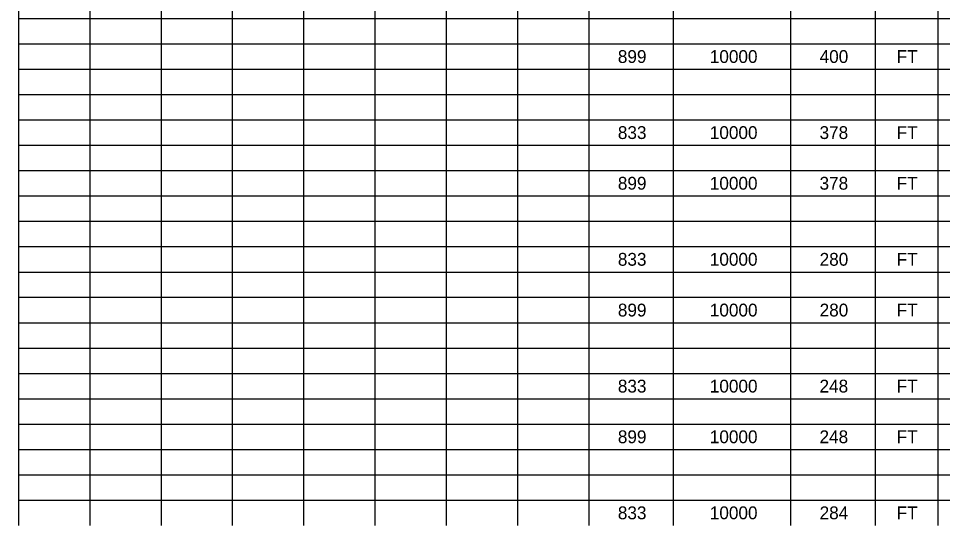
# Model space of a CAD drawing. Extents: x 0.2 to 34.2, y 0 to 22.
# Drawn here: x 13.45 to 23.52, y 10.48 to 16.02 of the extents above; entities that cross this region are included whole.
import ezdxf

# ---------------------------------------------------------------- set-up
doc = ezdxf.new("R2010")
doc.units = 0
doc.layers.add('Default', color=7, linetype='Continuous')

msp = doc.modelspace()

# ---------------------------------------------------------------- linework, layer by layer
at = {"layer": 'Default'}
for p, q in [((13.445, 16.294), (13.445, 16.018)), ((14.223, 16.294), (14.223, 16.018)), ((15, 16.294), (15, 16.018)), ((15.778, 16.294), (15.778, 16.018)), ((16.555, 16.294), (16.555, 16.018)), ((17.332, 16.294), (17.332, 16.018)), ((18.11, 16.294), (18.11, 16.018)), ((18.887, 16.294), (18.887, 16.018)), ((19.665, 16.294), (19.665, 16.018)), ((20.587, 16.294), (20.587, 16.018)), ((21.865, 16.294), (21.865, 16.018)), ((22.788, 16.294), (22.788, 16.018)), ((23.473, 16.294), (23.473, 16.018)), ((13.445, 16.018), (14.223, 16.018)), ((13.445, 16.018), (13.445, 15.741)), ((14.223, 16.018), (16.555, 16.018)), ((14.223, 16.018), (14.223, 15.741)), ((15, 16.018), (15, 15.741)), ((15.778, 16.018), (15.778, 15.741)), ((16.555, 16.018), (32.196, 16.018)), ((16.555, 16.018), (16.555, 15.741)), ((17.332, 16.018), (17.332, 15.741)), ((18.11, 16.018), (18.11, 15.741)), ((18.887, 16.018), (18.887, 15.741)), ((19.665, 16.018), (19.665, 15.741)), ((20.587, 16.018), (20.587, 15.741)), ((21.865, 16.018), (21.865, 15.741)), ((22.788, 16.018), (22.788, 15.741)), ((23.473, 16.018), (23.473, 15.741)), ((13.445, 15.741), (14.223, 15.741)), ((13.445, 15.741), (13.445, 15.464)), ((14.223, 15.741), (16.555, 15.741)), ((14.223, 15.741), (14.223, 15.464)), ((15, 15.741), (15, 15.464)), ((15.778, 15.741), (15.778, 15.464)), ((16.555, 15.741), (32.196, 15.741)), ((16.555, 15.741), (16.555, 15.464)), ((17.332, 15.741), (17.332, 15.464)), ((18.11, 15.741), (18.11, 15.464)), ((18.887, 15.741), (18.887, 15.464)), ((19.665, 15.741), (19.665, 15.464)), ((20.587, 15.741), (20.587, 15.464)), ((21.865, 15.741), (21.865, 15.464)), ((22.788, 15.741), (22.788, 15.464)), ((23.473, 15.741), (23.473, 15.464)), ((13.445, 15.464), (14.223, 15.464)), ((13.445, 15.464), (13.445, 15.187)), ((14.223, 15.464), (16.555, 15.464)), ((14.223, 15.464), (14.223, 15.187)), ((15, 15.464), (15, 15.187)), ((15.778, 15.464), (15.778, 15.187)), ((16.555, 15.464), (32.196, 15.464)), ((16.555, 15.464), (16.555, 15.187)), ((17.332, 15.464), (17.332, 15.187)), ((18.11, 15.464), (18.11, 15.187)), ((18.887, 15.464), (18.887, 15.187)), ((19.665, 15.464), (19.665, 15.187)), ((20.587, 15.464), (20.587, 15.187)), ((21.865, 15.464), (21.865, 15.187)), ((22.788, 15.464), (22.788, 15.187)), ((23.473, 15.464), (23.473, 15.187)), ((13.445, 15.187), (14.223, 15.187)), ((13.445, 15.187), (13.445, 14.911)), ((14.223, 15.187), (16.555, 15.187)), ((14.223, 15.187), (14.223, 14.911)), ((15, 15.187), (15, 14.911)), ((15.778, 15.187), (15.778, 14.911)), ((16.555, 15.187), (32.196, 15.187)), ((16.555, 15.187), (16.555, 14.911)), ((17.332, 15.187), (17.332, 14.911)), ((18.11, 15.187), (18.11, 14.911)), ((18.887, 15.187), (18.887, 14.911)), ((19.665, 15.187), (19.665, 14.911)), ((20.587, 15.187), (20.587, 14.911)), ((21.865, 15.187), (21.865, 14.911)), ((22.788, 15.187), (22.788, 14.911)), ((23.473, 15.187), (23.473, 14.911)), ((13.445, 14.911), (14.223, 14.911)), ((13.445, 14.911), (13.445, 14.634)), ((14.223, 14.911), (16.555, 14.911)), ((14.223, 14.911), (14.223, 14.634)), ((15, 14.911), (15, 14.634)), ((15.778, 14.911), (15.778, 14.634)), ((16.555, 14.911), (32.196, 14.911)), ((16.555, 14.911), (16.555, 14.634)), ((17.332, 14.911), (17.332, 14.634)), ((18.11, 14.911), (18.11, 14.634)), ((18.887, 14.911), (18.887, 14.634)), ((19.665, 14.911), (19.665, 14.634)), ((20.587, 14.911), (20.587, 14.634)), ((21.865, 14.911), (21.865, 14.634)), ((22.788, 14.911), (22.788, 14.634)), ((23.473, 14.911), (23.473, 14.634)), ((13.445, 14.634), (14.223, 14.634)), ((13.445, 14.634), (13.445, 14.357)), ((14.223, 14.634), (16.555, 14.634)), ((14.223, 14.634), (14.223, 14.357)), ((15, 14.634), (15, 14.357)), ((15.778, 14.634), (15.778, 14.357)), ((16.555, 14.634), (32.196, 14.634)), ((16.555, 14.634), (16.555, 14.357)), ((17.332, 14.634), (17.332, 14.357)), ((18.11, 14.634), (18.11, 14.357)), ((18.887, 14.634), (18.887, 14.357)), ((19.665, 14.634), (19.665, 14.357)), ((20.587, 14.634), (20.587, 14.357)), ((21.865, 14.634), (21.865, 14.357)), ((22.788, 14.634), (22.788, 14.357)), ((23.473, 14.634), (23.473, 14.357)), ((13.445, 14.357), (14.223, 14.357)), ((13.445, 14.357), (13.445, 14.081)), ((14.223, 14.357), (16.555, 14.357)), ((14.223, 14.357), (14.223, 14.081)), ((15, 14.357), (15, 14.081)), ((15.778, 14.357), (15.778, 14.081)), ((16.555, 14.357), (32.196, 14.357)), ((16.555, 14.357), (16.555, 14.081)), ((17.332, 14.357), (17.332, 14.081)), ((18.11, 14.357), (18.11, 14.081)), ((18.887, 14.357), (18.887, 14.081)), ((19.665, 14.357), (19.665, 14.081)), ((20.587, 14.357), (20.587, 14.081)), ((21.865, 14.357), (21.865, 14.081)), ((22.788, 14.357), (22.788, 14.081)), ((23.473, 14.357), (23.473, 14.081)), ((13.445, 14.081), (14.223, 14.081)), ((13.445, 14.081), (13.445, 13.804)), ((14.223, 14.081), (16.555, 14.081)), ((14.223, 14.081), (14.223, 13.804)), ((15, 14.081), (15, 13.804)), ((15.778, 14.081), (15.778, 13.804)), ((16.555, 14.081), (32.196, 14.081)), ((16.555, 14.081), (16.555, 13.804)), ((17.332, 14.081), (17.332, 13.804)), ((18.11, 14.081), (18.11, 13.804)), ((18.887, 14.081), (18.887, 13.804)), ((19.665, 14.081), (19.665, 13.804)), ((20.587, 14.081), (20.587, 13.804)), ((21.865, 14.081), (21.865, 13.804)), ((22.788, 14.081), (22.788, 13.804)), ((23.473, 14.081), (23.473, 13.804)), ((13.445, 13.804), (14.223, 13.804)), ((13.445, 13.804), (13.445, 13.527)), ((14.223, 13.804), (16.555, 13.804)), ((14.223, 13.804), (14.223, 13.527)), ((15, 13.804), (15, 13.527)), ((15.778, 13.804), (15.778, 13.527)), ((16.555, 13.804), (32.196, 13.804)), ((16.555, 13.804), (16.555, 13.527)), ((17.332, 13.804), (17.332, 13.527)), ((18.11, 13.804), (18.11, 13.527)), ((18.887, 13.804), (18.887, 13.527)), ((19.665, 13.804), (19.665, 13.527)), ((20.587, 13.804), (20.587, 13.527)), ((21.865, 13.804), (21.865, 13.527)), ((22.788, 13.804), (22.788, 13.527)), ((23.473, 13.804), (23.473, 13.527)), ((13.445, 13.527), (14.223, 13.527)), ((13.445, 13.527), (13.445, 13.25)), ((14.223, 13.527), (16.555, 13.527)), ((14.223, 13.527), (14.223, 13.25)), ((15, 13.527), (15, 13.25)), ((15.778, 13.527), (15.778, 13.25)), ((16.555, 13.527), (32.196, 13.527)), ((16.555, 13.527), (16.555, 13.25)), ((17.332, 13.527), (17.332, 13.25)), ((18.11, 13.527), (18.11, 13.25)), ((18.887, 13.527), (18.887, 13.25)), ((19.665, 13.527), (19.665, 13.25)), ((20.587, 13.527), (20.587, 13.25)), ((21.865, 13.527), (21.865, 13.25)), ((22.788, 13.527), (22.788, 13.25)), ((23.473, 13.527), (23.473, 13.25)), ((13.445, 13.25), (14.223, 13.25)), ((13.445, 13.25), (13.445, 12.974)), ((14.223, 13.25), (16.555, 13.25)), ((14.223, 13.25), (14.223, 12.974)), ((15, 13.25), (15, 12.974)), ((15.778, 13.25), (15.778, 12.974)), ((16.555, 13.25), (32.196, 13.25)), ((16.555, 13.25), (16.555, 12.974)), ((17.332, 13.25), (17.332, 12.974)), ((18.11, 13.25), (18.11, 12.974)), ((18.887, 13.25), (18.887, 12.974)), ((19.665, 13.25), (19.665, 12.974)), ((20.587, 13.25), (20.587, 12.974)), ((21.865, 13.25), (21.865, 12.974)), ((22.788, 13.25), (22.788, 12.974)), ((23.473, 13.25), (23.473, 12.974)), ((13.445, 12.974), (14.223, 12.974)), ((13.445, 12.974), (13.445, 12.697)), ((14.223, 12.974), (16.555, 12.974)), ((14.223, 12.974), (14.223, 12.697)), ((15, 12.974), (15, 12.697)), ((15.778, 12.974), (15.778, 12.697)), ((16.555, 12.974), (32.196, 12.974)), ((16.555, 12.974), (16.555, 12.697)), ((17.332, 12.974), (17.332, 12.697)), ((18.11, 12.974), (18.11, 12.697)), ((18.887, 12.974), (18.887, 12.697)), ((19.665, 12.974), (19.665, 12.697)), ((20.587, 12.974), (20.587, 12.697)), ((21.865, 12.974), (21.865, 12.697)), ((22.788, 12.974), (22.788, 12.697)), ((23.473, 12.974), (23.473, 12.697)), ((13.445, 12.697), (14.223, 12.697)), ((13.445, 12.697), (13.445, 12.42)), ((14.223, 12.697), (16.555, 12.697)), ((14.223, 12.697), (14.223, 12.42)), ((15, 12.697), (15, 12.42)), ((15.778, 12.697), (15.778, 12.42)), ((16.555, 12.697), (32.196, 12.697)), ((16.555, 12.697), (16.555, 12.42)), ((17.332, 12.697), (17.332, 12.42)), ((18.11, 12.697), (18.11, 12.42)), ((18.887, 12.697), (18.887, 12.42)), ((19.665, 12.697), (19.665, 12.42)), ((20.587, 12.697), (20.587, 12.42)), ((21.865, 12.697), (21.865, 12.42)), ((22.788, 12.697), (22.788, 12.42)), ((23.473, 12.697), (23.473, 12.42)), ((13.445, 12.42), (14.223, 12.42)), ((13.445, 12.42), (13.445, 12.144)), ((14.223, 12.42), (16.555, 12.42)), ((14.223, 12.42), (14.223, 12.144)), ((15, 12.42), (15, 12.144)), ((15.778, 12.42), (15.778, 12.144)), ((16.555, 12.42), (32.196, 12.42)), ((16.555, 12.42), (16.555, 12.144)), ((17.332, 12.42), (17.332, 12.144)), ((18.11, 12.42), (18.11, 12.144)), ((18.887, 12.42), (18.887, 12.144)), ((19.665, 12.42), (19.665, 12.144)), ((20.587, 12.42), (20.587, 12.144)), ((21.865, 12.42), (21.865, 12.144)), ((22.788, 12.42), (22.788, 12.144)), ((23.473, 12.42), (23.473, 12.144)), ((13.445, 12.144), (14.223, 12.144)), ((13.445, 12.144), (13.445, 11.867)), ((14.223, 12.144), (16.555, 12.144)), ((14.223, 12.144), (14.223, 11.867)), ((15, 12.144), (15, 11.867)), ((15.778, 12.144), (15.778, 11.867)), ((16.555, 12.144), (32.196, 12.144)), ((16.555, 12.144), (16.555, 11.867)), ((17.332, 12.144), (17.332, 11.867)), ((18.11, 12.144), (18.11, 11.867)), ((18.887, 12.144), (18.887, 11.867)), ((19.665, 12.144), (19.665, 11.867)), ((20.587, 12.144), (20.587, 11.867)), ((21.865, 12.144), (21.865, 11.867)), ((22.788, 12.144), (22.788, 11.867)), ((23.473, 12.144), (23.473, 11.867)), ((13.445, 11.867), (14.223, 11.867)), ((13.445, 11.867), (13.445, 11.59)), ((14.223, 11.867), (16.555, 11.867)), ((14.223, 11.867), (14.223, 11.59)), ((15, 11.867), (15, 11.59)), ((15.778, 11.867), (15.778, 11.59)), ((16.555, 11.867), (32.196, 11.867)), ((16.555, 11.867), (16.555, 11.59)), ((17.332, 11.867), (17.332, 11.59)), ((18.11, 11.867), (18.11, 11.59)), ((18.887, 11.867), (18.887, 11.59)), ((19.665, 11.867), (19.665, 11.59)), ((20.587, 11.867), (20.587, 11.59)), ((21.865, 11.867), (21.865, 11.59)), ((22.788, 11.867), (22.788, 11.59)), ((23.473, 11.867), (23.473, 11.59)), ((13.445, 11.59), (14.223, 11.59)), ((13.445, 11.59), (13.445, 11.314)), ((14.223, 11.59), (16.555, 11.59)), ((14.223, 11.59), (14.223, 11.314)), ((15, 11.59), (15, 11.314)), ((15.778, 11.59), (15.778, 11.314)), ((16.555, 11.59), (32.196, 11.59)), ((16.555, 11.59), (16.555, 11.314)), ((17.332, 11.59), (17.332, 11.314)), ((18.11, 11.59), (18.11, 11.314)), ((18.887, 11.59), (18.887, 11.314)), ((19.665, 11.59), (19.665, 11.314)), ((20.587, 11.59), (20.587, 11.314)), ((21.865, 11.59), (21.865, 11.314)), ((22.788, 11.59), (22.788, 11.314)), ((23.473, 11.59), (23.473, 11.314)), ((13.445, 11.314), (14.223, 11.314)), ((13.445, 11.314), (13.445, 11.037)), ((14.223, 11.314), (16.555, 11.314)), ((14.223, 11.314), (14.223, 11.037)), ((15, 11.314), (15, 11.037)), ((15.778, 11.314), (15.778, 11.037)), ((16.555, 11.314), (32.196, 11.314)), ((16.555, 11.314), (16.555, 11.037)), ((17.332, 11.314), (17.332, 11.037)), ((18.11, 11.314), (18.11, 11.037)), ((18.887, 11.314), (18.887, 11.037)), ((19.665, 11.314), (19.665, 11.037)), ((20.587, 11.314), (20.587, 11.037)), ((21.865, 11.314), (21.865, 11.037)), ((22.788, 11.314), (22.788, 11.037)), ((23.473, 11.314), (23.473, 11.037)), ((13.445, 11.037), (14.223, 11.037)), ((13.445, 11.037), (13.445, 10.76)), ((14.223, 11.037), (16.555, 11.037)), ((14.223, 11.037), (14.223, 10.76)), ((15, 11.037), (15, 10.76)), ((15.778, 11.037), (15.778, 10.76)), ((16.555, 11.037), (32.196, 11.037)), ((16.555, 11.037), (16.555, 10.76)), ((17.332, 11.037), (17.332, 10.76)), ((18.11, 11.037), (18.11, 10.76)), ((18.887, 11.037), (18.887, 10.76)), ((19.665, 11.037), (19.665, 10.76)), ((20.587, 11.037), (20.587, 10.76)), ((21.865, 11.037), (21.865, 10.76)), ((22.788, 11.037), (22.788, 10.76)), ((23.473, 11.037), (23.473, 10.76)), ((13.445, 10.76), (14.223, 10.76)), ((13.445, 10.76), (13.445, 10.483)), ((14.223, 10.76), (16.555, 10.76)), ((14.223, 10.76), (14.223, 10.483)), ((15, 10.76), (15, 10.483)), ((15.778, 10.76), (15.778, 10.483)), ((16.555, 10.76), (32.196, 10.76)), ((16.555, 10.76), (16.555, 10.483)), ((17.332, 10.76), (17.332, 10.483)), ((18.11, 10.76), (18.11, 10.483)), ((18.887, 10.76), (18.887, 10.483)), ((19.665, 10.76), (19.665, 10.483)), ((20.587, 10.76), (20.587, 10.483)), ((21.865, 10.76), (21.865, 10.483)), ((22.788, 10.76), (22.788, 10.483)), ((23.473, 10.76), (23.473, 10.483))]:
    msp.add_line(p, q, dxfattribs=at)

# ---------------------------------------------------------------- texts
for s, p in [('899', (19.983, 15.532)), ('10000', (20.986, 15.532)), ('400', (22.184, 15.532)), ('FT', (23.024, 15.532)), ('833', (19.983, 14.702)), ('10000', (20.986, 14.702)), ('378', (22.183, 14.702)), ('FT', (23.024, 14.702)), ('899', (19.983, 14.149)), ('10000', (20.986, 14.149)), ('378', (22.183, 14.149)), ('FT', (23.024, 14.149)), ('833', (19.983, 13.319)), ('10000', (20.986, 13.319)), ('280', (22.184, 13.319)), ('FT', (23.024, 13.319)), ('899', (19.983, 12.765)), ('10000', (20.986, 12.765)), ('280', (22.184, 12.765)), ('FT', (23.024, 12.765)), ('833', (19.983, 11.935)), ('10000', (20.986, 11.935)), ('248', (22.183, 11.935)), ('FT', (23.024, 11.935)), ('899', (19.983, 11.382)), ('10000', (20.986, 11.382)), ('248', (22.183, 11.382)), ('FT', (23.024, 11.382)), ('833', (19.983, 10.552)), ('10000', (20.986, 10.552)), ('284', (22.184, 10.552)), ('FT', (23.024, 10.552))]:
    msp.add_text(s, height=0.14, dxfattribs=at).set_placement(p)

doc.saveas('drawing.dxf')
